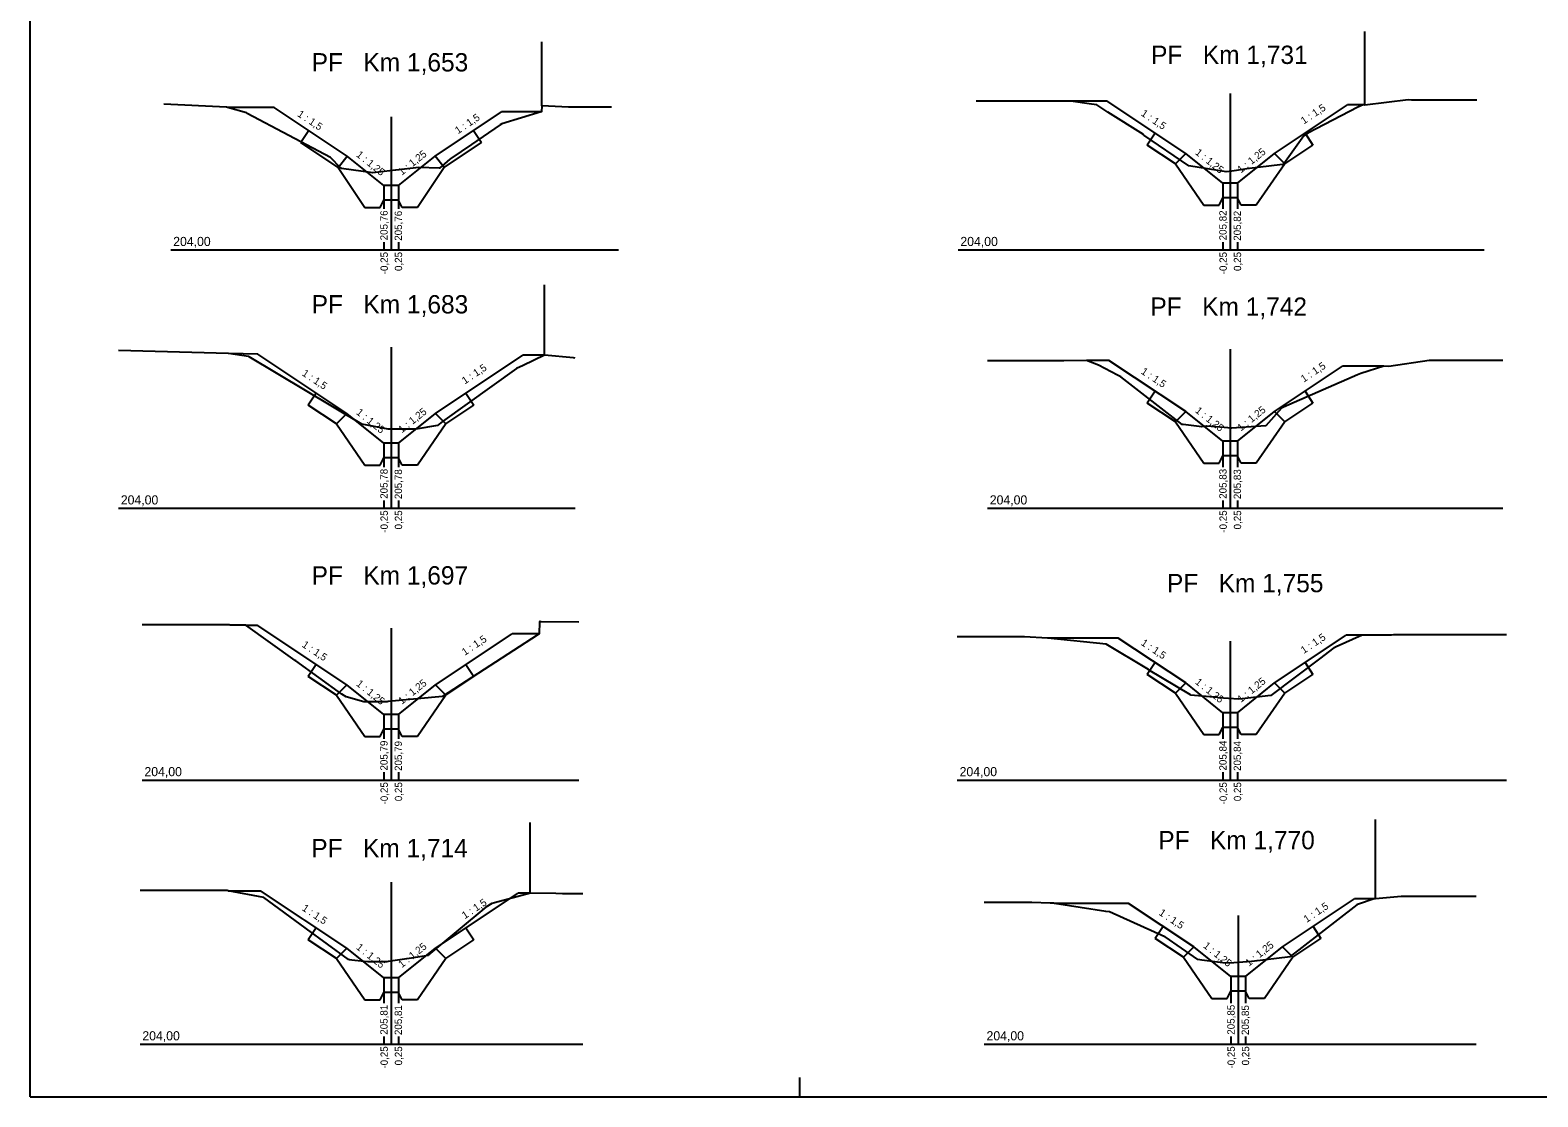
# Model space of a CAD drawing. Extents: x -547174 to -543113, y -1125006 to -1123643.
# Drawn here: x -547152.27 to -547111.11, y -1123837.37 to -1123808.23 of the extents above; entities that cross this region are included whole.
import ezdxf

# ---------------------------------------------------------------- set-up
doc = ezdxf.new("R2010")
doc.units = 0
for name, color, linetype in [('Default', 7, 'Continuous'), ('Profile', 7, 'Continuous'), ('PROFILY NÁVRH', 7, 'Continuous'), ('Section', 7, 'Continuous'), ('STANIČENÍ', 7, 'Continuous')]:
    doc.layers.add(name, color=color, linetype=linetype)

msp = doc.modelspace()

# ---------------------------------------------------------------- linework, layer by layer
at = {"layer": 'Default'}
for points in [[(-547136.405, -1123810.332), (-547137.568, -1123810.332), (-547137.573, -1123810.332), (-547138.304, -1123810.302), (-547138.315, -1123810.461), (-547138.326, -1123810.463), (-547139.398, -1123810.787), (-547139.438, -1123810.819), (-547140.228, -1123811.356), (-547140.789, -1123811.738), (-547140.818, -1123811.755), (-547141.1, -1123812.004), (-547141.1, -1123812.004), (-547141.102, -1123812.005), (-547141.662, -1123811.986), (-547141.665, -1123811.985), (-547142.292, -1123812.06), (-547142.296, -1123812.06), (-547142.92, -1123812.134), (-547143.769, -1123812.007), (-547143.79, -1123812.004), (-547144.072, -1123811.708), (-547146.344, -1123810.506), (-547146.366, -1123810.492), (-547146.368, -1123810.492), (-547146.886, -1123810.341), (-547146.909, -1123810.34), (-547148.627, -1123810.253)], [(-547112.776, -1123810.142), (-547114.563, -1123810.142), (-547114.649, -1123810.135), (-547115.838, -1123810.283), (-547115.868, -1123810.276), (-547115.884, -1123810.274), (-547116.029, -1123810.34), (-547117.389, -1123811.045), (-547117.497, -1123811.12), (-547118.049, -1123811.886), (-547118.06, -1123811.9), (-547118.082, -1123811.905), (-547119.054, -1123812.023), (-547119.34, -1123812.063), (-547119.341, -1123812.063), (-547119.463, -1123812.081), (-547119.62, -1123812.103), (-547120.637, -1123811.934), (-547120.637, -1123811.934), (-547121.868, -1123811.097), (-547121.882, -1123811.085), (-547122.856, -1123810.469), (-547123.156, -1123810.275), (-547123.158, -1123810.274), (-547123.159, -1123810.274), (-547123.364, -1123810.245), (-547123.866, -1123810.174), (-547123.899, -1123810.174), (-547126.444, -1123810.175)], [(-547137.392, -1123817.193), (-547137.44, -1123817.18), (-547138.228, -1123817.113), (-547138.809, -1123817.389), (-547138.997, -1123817.47), (-547141.014, -1123818.919), (-547141.154, -1123819.033), (-547141.74, -1123819.129), (-547141.762, -1123819.13), (-547142.117, -1123819.131), (-547142.125, -1123819.132), (-547142.48, -1123819.132), (-547142.486, -1123819.133), (-547142.5, -1123819.13), (-547143.218, -1123818.993), (-547146.289, -1123817.157), (-547146.311, -1123817.144), (-547146.854, -1123817.063), (-547146.854, -1123817.062), (-547146.857, -1123817.062), (-547149.86, -1123816.982)], [(-547112.067, -1123817.254), (-547114.077, -1123817.254), (-547115.178, -1123817.415), (-547115.316, -1123817.413), (-547115.944, -1123817.607), (-547116.037, -1123817.649), (-547118.053, -1123818.526), (-547118.111, -1123818.557), (-547118.542, -1123819.04), (-547118.543, -1123819.042), (-547119.47, -1123819.101), (-547119.477, -1123819.102), (-547119.675, -1123819.089), (-547120.151, -1123819.052), (-547120.156, -1123819.052), (-547120.282, -1123819.071), (-547120.791, -1123819.004), (-547120.819, -1123819.001), (-547122.495, -1123817.704), (-547122.497, -1123817.703), (-547122.584, -1123817.659), (-547123.107, -1123817.382), (-547123.433, -1123817.253), (-547124.051, -1123817.263), (-547124.062, -1123817.262), (-547126.138, -1123817.262)], [(-547137.295, -1123824.402), (-547138.333, -1123824.389), (-547138.351, -1123824.387), (-547138.369, -1123824.396), (-547138.374, -1123824.716), (-547138.427, -1123824.754), (-547141.013, -1123826.435), (-547142.5, -1123826.57), (-547142.522, -1123826.573), (-547142.857, -1123826.574), (-547142.864, -1123826.574), (-547143.157, -1123826.574), (-547143.164, -1123826.574), (-547143.647, -1123826.444), (-547143.648, -1123826.444), (-547143.759, -1123826.366), (-547145.02, -1123825.461), (-547145.04, -1123825.446), (-547146.384, -1123824.482), (-547146.81, -1123824.481), (-547146.839, -1123824.475), (-547147.014, -1123824.475), (-547149.215, -1123824.475)], [(-547111.971, -1123824.75), (-547115.052, -1123824.75), (-547115.108, -1123824.758), (-547115.91, -1123824.757), (-547116.616, -1123825.076), (-547116.675, -1123825.104), (-547116.678, -1123825.106), (-547117.069, -1123825.4), (-547118.4, -1123826.404), (-547119.184, -1123826.494), (-547119.271, -1123826.504), (-547119.557, -1123826.484), (-547119.559, -1123826.484), (-547119.844, -1123826.464), (-547119.849, -1123826.464), (-547119.859, -1123826.463), (-547120.583, -1123826.394), (-547120.591, -1123826.389), (-547121.737, -1123825.699), (-547121.746, -1123825.695), (-547122.894, -1123825.004), (-547124.49, -1123824.835), (-547124.495, -1123824.834), (-547124.497, -1123824.834), (-547125.131, -1123824.804), (-547125.191, -1123824.804), (-547126.961, -1123824.805)], [(-547137.184, -1123831.824), (-547137.741, -1123831.824), (-547137.923, -1123831.809), (-547138.615, -1123831.803), (-547139.598, -1123832.063), (-547139.673, -1123832.085), (-547139.828, -1123832.183), (-547141.396, -1123833.491), (-547141.409, -1123833.507), (-547141.864, -1123833.575), (-547142.495, -1123833.672), (-547142.501, -1123833.666), (-547142.539, -1123833.679), (-547142.84, -1123833.679), (-547142.842, -1123833.679), (-547143.056, -1123833.679), (-547143.057, -1123833.679), (-547143.152, -1123833.67), (-547143.488, -1123833.632), (-547143.557, -1123833.628), (-547143.579, -1123833.614), (-547144.724, -1123832.774), (-547144.765, -1123832.747), (-547145.894, -1123831.921), (-547146.865, -1123831.737), (-547146.891, -1123831.734), (-547147.073, -1123831.733), (-547149.272, -1123831.734)], [(-547112.8, -1123831.891), (-547114.844, -1123831.891), (-547115.547, -1123831.959), (-547115.581, -1123831.959), (-547116.04, -1123832.115), (-547116.058, -1123832.123), (-547117.552, -1123833.29), (-547117.87, -1123833.536), (-547117.873, -1123833.539), (-547118.922, -1123833.667), (-547118.93, -1123833.669), (-547118.933, -1123833.669), (-547119.286, -1123833.694), (-547119.286, -1123833.694), (-547119.416, -1123833.703), (-547119.643, -1123833.718), (-547120.286, -1123833.633), (-547120.393, -1123833.619), (-547121.291, -1123833), (-547121.294, -1123832.998), (-547121.298, -1123832.996), (-547122.803, -1123832.315), (-547122.909, -1123832.301), (-547124.312, -1123832.082), (-547124.334, -1123832.079), (-547124.422, -1123832.076), (-547124.924, -1123832.059), (-547124.927, -1123832.058), (-547126.226, -1123832.058)]]:
    msp.add_lwpolyline(points, dxfattribs=at)
at = {"layer": 'Profile'}
for p, q in [((-547152.272, -1123837.366), (-547152.272, -1123807.666)), ((-547131.272, -1123836.838), (-547131.272, -1123837.366)), ((-547152.272, -1123837.366), (-547131.272, -1123837.366)), ((-547131.272, -1123837.366), (-547110.272, -1123837.366))]:
    msp.add_line(p, q, dxfattribs=at)
at = {"layer": 'PROFILY NÁVRH'}
for p, q in [((-547145.614, -1123810.341), (-547146.886, -1123810.341)), ((-547143.615, -1123811.674), (-547145.614, -1123810.341)), ((-547122.867, -1123810.174), (-547123.866, -1123810.174)), ((-547120.725, -1123811.602), (-547122.867, -1123810.174)), ((-547118.301, -1123811.602), (-547116.309, -1123810.274)), ((-547115.884, -1123810.274), (-547116.309, -1123810.274)), ((-547141.22, -1123811.674), (-547139.403, -1123810.463)), ((-547138.326, -1123810.463), (-547139.403, -1123810.463)), ((-547144.663, -1123810.975), (-547144.88, -1123811.302)), ((-547140.173, -1123810.975), (-547139.955, -1123811.302)), ((-547121.557, -1123811.048), (-547121.775, -1123811.374)), ((-547117.469, -1123811.048), (-547117.252, -1123811.374)), ((-547143.861, -1123811.981), (-547144.88, -1123811.302)), ((-547140.974, -1123811.981), (-547139.955, -1123811.302)), ((-547121.008, -1123811.885), (-547121.775, -1123811.374)), ((-547121.008, -1123811.885), (-547120.725, -1123811.602)), ((-547119.713, -1123812.414), (-547120.725, -1123811.602)), ((-547119.313, -1123812.414), (-547118.301, -1123811.602)), ((-547118.018, -1123811.885), (-547118.301, -1123811.602)), ((-547118.018, -1123811.885), (-547117.252, -1123811.374)), ((-547143.861, -1123811.981), (-547143.615, -1123811.674)), ((-547143.861, -1123811.981), (-547143.133, -1123813.074)), ((-547142.618, -1123812.474), (-547143.615, -1123811.674)), ((-547142.218, -1123812.474), (-547141.22, -1123811.674)), ((-547140.974, -1123811.981), (-547141.702, -1123813.074)), ((-547140.974, -1123811.981), (-547141.22, -1123811.674)), ((-547121.008, -1123811.885), (-547120.228, -1123813.014)), ((-547118.018, -1123811.885), (-547118.798, -1123813.014)), ((-547119.313, -1123812.414), (-547119.713, -1123812.414)), ((-547119.713, -1123812.414), (-547119.713, -1123813.11)), ((-547119.313, -1123812.414), (-547119.313, -1123813.11)), ((-547142.718, -1123813.074), (-547142.618, -1123812.874)), ((-547142.218, -1123812.474), (-547142.618, -1123812.474)), ((-547142.618, -1123812.474), (-547142.618, -1123813.11)), ((-547142.218, -1123812.874), (-547142.618, -1123812.874)), ((-547142.218, -1123812.474), (-547142.218, -1123813.11)), ((-547142.118, -1123813.074), (-547142.218, -1123812.874)), ((-547119.813, -1123813.014), (-547119.713, -1123812.814)), ((-547119.313, -1123812.814), (-547119.713, -1123812.814)), ((-547119.213, -1123813.014), (-547119.313, -1123812.814)), ((-547143.133, -1123813.074), (-547142.718, -1123813.074)), ((-547141.702, -1123813.074), (-547142.118, -1123813.074)), ((-547120.228, -1123813.014), (-547119.813, -1123813.014)), ((-547118.798, -1123813.014), (-547119.213, -1123813.014)), ((-547142.618, -1123814.022), (-547142.618, -1123814.234)), ((-547142.218, -1123814.022), (-547142.218, -1123814.234)), ((-547119.713, -1123814.022), (-547119.713, -1123814.234)), ((-547119.313, -1123814.022), (-547119.313, -1123814.234)), ((-547146.054, -1123817.084), (-547146.857, -1123817.062)), ((-547143.629, -1123818.7), (-547146.054, -1123817.084)), ((-547141.206, -1123818.7), (-547138.825, -1123817.113)), ((-547138.228, -1123817.113), (-547138.825, -1123817.113)), ((-547122.82, -1123817.253), (-547123.433, -1123817.253)), ((-547120.725, -1123818.65), (-547122.82, -1123817.253)), ((-547118.301, -1123818.65), (-547116.445, -1123817.413)), ((-547115.316, -1123817.413), (-547116.445, -1123817.413)), ((-547144.461, -1123818.146), (-547144.679, -1123818.472)), ((-547140.374, -1123818.146), (-547140.156, -1123818.472)), ((-547121.557, -1123818.096), (-547121.775, -1123818.422)), ((-547117.469, -1123818.096), (-547117.252, -1123818.422)), ((-547143.912, -1123818.983), (-547144.679, -1123818.472)), ((-547140.923, -1123818.983), (-547140.156, -1123818.472)), ((-547121.008, -1123818.933), (-547121.775, -1123818.422)), ((-547118.018, -1123818.933), (-547117.252, -1123818.422)), ((-547143.912, -1123818.983), (-547143.629, -1123818.7)), ((-547143.912, -1123818.983), (-547143.133, -1123820.112)), ((-547142.618, -1123819.512), (-547143.629, -1123818.7)), ((-547142.218, -1123819.512), (-547141.206, -1123818.7)), ((-547140.923, -1123818.983), (-547141.702, -1123820.112)), ((-547140.923, -1123818.983), (-547141.206, -1123818.7)), ((-547121.008, -1123818.933), (-547120.725, -1123818.65)), ((-547121.008, -1123818.933), (-547120.228, -1123820.062)), ((-547119.713, -1123819.462), (-547120.725, -1123818.65)), ((-547119.313, -1123819.462), (-547118.301, -1123818.65)), ((-547118.018, -1123818.933), (-547118.798, -1123820.062)), ((-547118.018, -1123818.933), (-547118.301, -1123818.65)), ((-547119.313, -1123819.462), (-547119.713, -1123819.462)), ((-547119.713, -1123819.462), (-547119.713, -1123820.168)), ((-547119.313, -1123819.462), (-547119.313, -1123820.168)), ((-547142.218, -1123819.512), (-547142.618, -1123819.512)), ((-547142.618, -1123819.512), (-547142.618, -1123820.168)), ((-547142.218, -1123819.512), (-547142.218, -1123820.168)), ((-547119.813, -1123820.062), (-547119.713, -1123819.862)), ((-547119.313, -1123819.862), (-547119.713, -1123819.862)), ((-547119.213, -1123820.062), (-547119.313, -1123819.862)), ((-547143.133, -1123820.112), (-547142.718, -1123820.112)), ((-547142.718, -1123820.112), (-547142.618, -1123819.912)), ((-547142.218, -1123819.912), (-547142.618, -1123819.912)), ((-547142.118, -1123820.112), (-547142.218, -1123819.912)), ((-547141.702, -1123820.112), (-547142.118, -1123820.112)), ((-547120.228, -1123820.062), (-547119.813, -1123820.062)), ((-547118.798, -1123820.062), (-547119.213, -1123820.062)), ((-547142.618, -1123821.08), (-547142.618, -1123821.292)), ((-547142.218, -1123821.08), (-547142.218, -1123821.292)), ((-547119.713, -1123821.08), (-547119.713, -1123821.292)), ((-547119.313, -1123821.08), (-547119.313, -1123821.292)), ((-547146.384, -1123824.482), (-547146.075, -1123824.482)), ((-547143.629, -1123826.112), (-547146.075, -1123824.482)), ((-547141.206, -1123826.112), (-547139.111, -1123824.716)), ((-547138.374, -1123824.716), (-547139.111, -1123824.716)), ((-547118.301, -1123826.062), (-547116.344, -1123824.757)), ((-547115.91, -1123824.757), (-547116.344, -1123824.757)), ((-547122.566, -1123824.835), (-547124.49, -1123824.835)), ((-547120.725, -1123826.062), (-547122.566, -1123824.835)), ((-547144.461, -1123825.557), (-547144.679, -1123825.884)), ((-547140.374, -1123825.557), (-547140.156, -1123825.884)), ((-547121.557, -1123825.507), (-547121.775, -1123825.834)), ((-547117.469, -1123825.507), (-547117.252, -1123825.834)), ((-547143.912, -1123826.395), (-547144.679, -1123825.884)), ((-547140.923, -1123826.395), (-547140.156, -1123825.884)), ((-547121.008, -1123826.345), (-547121.775, -1123825.834)), ((-547118.018, -1123826.345), (-547117.252, -1123825.834)), ((-547143.912, -1123826.395), (-547143.629, -1123826.112)), ((-547143.912, -1123826.395), (-547143.133, -1123827.524)), ((-547142.618, -1123826.924), (-547143.629, -1123826.112)), ((-547142.218, -1123826.924), (-547141.206, -1123826.112)), ((-547140.923, -1123826.395), (-547141.702, -1123827.524)), ((-547140.923, -1123826.395), (-547141.206, -1123826.112)), ((-547121.008, -1123826.345), (-547120.725, -1123826.062)), ((-547121.008, -1123826.345), (-547120.228, -1123827.474)), ((-547119.713, -1123826.874), (-547120.725, -1123826.062)), ((-547119.313, -1123826.874), (-547118.301, -1123826.062)), ((-547118.018, -1123826.345), (-547118.798, -1123827.474)), ((-547118.018, -1123826.345), (-547118.301, -1123826.062)), ((-547119.313, -1123826.874), (-547119.713, -1123826.874)), ((-547119.713, -1123826.874), (-547119.713, -1123827.59)), ((-547119.313, -1123826.874), (-547119.313, -1123827.59)), ((-547142.218, -1123826.924), (-547142.618, -1123826.924)), ((-547142.618, -1123826.924), (-547142.618, -1123827.59)), ((-547142.218, -1123826.924), (-547142.218, -1123827.59)), ((-547119.813, -1123827.474), (-547119.713, -1123827.274)), ((-547119.313, -1123827.274), (-547119.713, -1123827.274)), ((-547119.213, -1123827.474), (-547119.313, -1123827.274)), ((-547143.133, -1123827.524), (-547142.718, -1123827.524)), ((-547142.718, -1123827.524), (-547142.618, -1123827.324)), ((-547142.218, -1123827.324), (-547142.618, -1123827.324)), ((-547142.118, -1123827.524), (-547142.218, -1123827.324)), ((-547141.702, -1123827.524), (-547142.118, -1123827.524)), ((-547120.228, -1123827.474), (-547119.813, -1123827.474)), ((-547118.798, -1123827.474), (-547119.213, -1123827.474)), ((-547142.618, -1123828.502), (-547142.618, -1123828.714)), ((-547142.218, -1123828.502), (-547142.218, -1123828.714)), ((-547119.713, -1123828.502), (-547119.713, -1123828.714)), ((-547119.313, -1123828.502), (-547119.313, -1123828.714)), ((-547146.865, -1123831.737), (-547145.984, -1123831.737)), ((-547143.629, -1123833.307), (-547145.984, -1123831.737)), ((-547141.206, -1123833.307), (-547138.95, -1123831.803)), ((-547138.615, -1123831.803), (-547138.95, -1123831.803)), ((-547122.284, -1123832.082), (-547124.312, -1123832.082)), ((-547120.506, -1123833.267), (-547122.284, -1123832.082)), ((-547118.082, -1123833.267), (-547116.12, -1123831.959)), ((-547115.581, -1123831.959), (-547116.12, -1123831.959)), ((-547144.461, -1123832.752), (-547144.679, -1123833.078)), ((-547140.374, -1123832.752), (-547140.156, -1123833.078)), ((-547121.338, -1123832.712), (-547121.555, -1123833.038)), ((-547120.789, -1123833.55), (-547121.555, -1123833.038)), ((-547117.799, -1123833.55), (-547117.033, -1123833.038)), ((-547117.25, -1123832.712), (-547117.033, -1123833.038)), ((-547143.912, -1123833.59), (-547144.679, -1123833.078)), ((-547143.912, -1123833.59), (-547143.629, -1123833.307)), ((-547142.618, -1123834.119), (-547143.629, -1123833.307)), ((-547142.218, -1123834.119), (-547141.206, -1123833.307)), ((-547140.923, -1123833.59), (-547141.206, -1123833.307)), ((-547140.923, -1123833.59), (-547140.156, -1123833.078)), ((-547120.789, -1123833.55), (-547120.506, -1123833.267)), ((-547119.494, -1123834.079), (-547120.506, -1123833.267)), ((-547119.094, -1123834.079), (-547118.082, -1123833.267)), ((-547117.799, -1123833.55), (-547118.082, -1123833.267)), ((-547143.912, -1123833.59), (-547143.133, -1123834.719)), ((-547140.923, -1123833.59), (-547141.702, -1123834.719)), ((-547120.789, -1123833.55), (-547120.009, -1123834.679)), ((-547117.799, -1123833.55), (-547118.579, -1123834.679)), ((-547142.218, -1123834.119), (-547142.618, -1123834.119)), ((-547142.618, -1123834.119), (-547142.618, -1123834.804)), ((-547142.218, -1123834.119), (-547142.218, -1123834.804)), ((-547119.094, -1123834.079), (-547119.494, -1123834.079)), ((-547119.494, -1123834.079), (-547119.494, -1123834.804)), ((-547119.094, -1123834.079), (-547119.094, -1123834.804)), ((-547142.718, -1123834.719), (-547142.618, -1123834.519)), ((-547142.218, -1123834.519), (-547142.618, -1123834.519)), ((-547142.118, -1123834.719), (-547142.218, -1123834.519)), ((-547120.009, -1123834.679), (-547119.594, -1123834.679)), ((-547119.594, -1123834.679), (-547119.494, -1123834.479)), ((-547119.094, -1123834.479), (-547119.494, -1123834.479)), ((-547118.994, -1123834.679), (-547119.094, -1123834.479)), ((-547118.579, -1123834.679), (-547118.994, -1123834.679)), ((-547143.133, -1123834.719), (-547142.718, -1123834.719)), ((-547141.702, -1123834.719), (-547142.118, -1123834.719)), ((-547142.618, -1123835.716), (-547142.618, -1123835.929)), ((-547142.218, -1123835.716), (-547142.218, -1123835.929)), ((-547119.494, -1123835.716), (-547119.494, -1123835.929)), ((-547119.094, -1123835.716), (-547119.094, -1123835.929))]:
    msp.add_line(p, q, dxfattribs=at)
at = {"layer": 'Section'}
for p, q in [((-547119.513, -1123809.966), (-547119.513, -1123814.234)), ((-547142.418, -1123810.602), (-547142.418, -1123814.234)), ((-547148.431, -1123814.234), (-547136.208, -1123814.234)), ((-547126.94, -1123814.234), (-547112.582, -1123814.234)), ((-547142.418, -1123816.892), (-547142.418, -1123821.292)), ((-547119.513, -1123816.947), (-547119.513, -1123821.292)), ((-547149.86, -1123821.292), (-547137.392, -1123821.292)), ((-547126.138, -1123821.292), (-547112.067, -1123821.292)), ((-547142.418, -1123824.564), (-547142.418, -1123828.714)), ((-547119.513, -1123824.919), (-547119.513, -1123828.714)), ((-547149.215, -1123828.714), (-547137.295, -1123828.714)), ((-547126.961, -1123828.714), (-547111.971, -1123828.714)), ((-547142.418, -1123831.501), (-547142.418, -1123835.929)), ((-547119.294, -1123832.41), (-547119.294, -1123835.929)), ((-547149.272, -1123835.929), (-547137.184, -1123835.929)), ((-547126.226, -1123835.929), (-547112.8, -1123835.929))]:
    msp.add_line(p, q, dxfattribs=at)
at = {"layer": 'STANIČENÍ'}
for p, q in [((-547115.838, -1123810.283), (-547115.838, -1123808.271)), ((-547138.304, -1123810.302), (-547138.304, -1123808.554)), ((-547138.228, -1123817.113), (-547138.228, -1123815.186)), ((-547138.618, -1123831.803), (-547138.618, -1123829.876)), ((-547115.547, -1123831.959), (-547115.547, -1123829.793))]:
    msp.add_line(p, q, dxfattribs=at)

# ---------------------------------------------------------------- texts
at = {"layer": 'PROFILY NÁVRH'}
for s, rotation, p in [('1 : 1,5', 33.6901, (-547117.501, -1123810.812)), ('1 : 1,5', 326.3099, (-547144.994, -1123810.57)), ('1 : 1,5', 33.6901, (-547140.592, -1123811.077)), ('1 : 1,5', 326.3099, (-547121.963, -1123810.551)), ('1 : 1,25', 321.2587, (-547143.388, -1123811.666)), ('1 : 1,25', 38.7413, (-547142.123, -1123812.208)), ('1 : 1,25', 321.2587, (-547120.483, -1123811.606)), ('1 : 1,25', 38.7413, (-547119.218, -1123812.148)), ('205,76', 90, (-547142.514, -1123813.974)), ('205,76', 90, (-547142.122, -1123813.985)), ('205,82', 90, (-547119.61, -1123813.974)), ('205,82', 90, (-547119.218, -1123813.985)), ('-0,25', 90, (-547142.508, -1123814.9)), ('0,25', 90, (-547142.117, -1123814.811)), ('-0,25', 90, (-547119.604, -1123814.9)), ('0,25', 90, (-547119.212, -1123814.811)), ('1 : 1,5', 33.6901, (-547140.405, -1123817.911)), ('1 : 1,5', 33.6901, (-547117.501, -1123817.861)), ('1 : 1,5', 326.3099, (-547144.868, -1123817.649)), ('1 : 1,5', 326.3099, (-547121.963, -1123817.599)), ('1 : 1,25', 321.2587, (-547143.388, -1123818.704)), ('1 : 1,25', 38.7413, (-547142.123, -1123819.246)), ('1 : 1,25', 321.2587, (-547120.483, -1123818.654)), ('1 : 1,25', 38.7413, (-547119.218, -1123819.196)), ('205,78', 90, (-547142.514, -1123821.032)), ('205,78', 90, (-547142.122, -1123821.043)), ('205,83', 90, (-547119.61, -1123821.032)), ('205,83', 90, (-547119.218, -1123821.043)), ('-0,25', 90, (-547142.508, -1123821.958)), ('0,25', 90, (-547142.117, -1123821.869)), ('-0,25', 90, (-547119.604, -1123821.958)), ('0,25', 90, (-547119.212, -1123821.869)), ('1 : 1,5', 33.6901, (-547140.405, -1123825.322)), ('1 : 1,5', 33.6901, (-547117.501, -1123825.272)), ('1 : 1,5', 326.3099, (-547144.868, -1123825.061)), ('1 : 1,5', 326.3099, (-547121.963, -1123825.011)), ('1 : 1,25', 321.2587, (-547143.388, -1123826.116)), ('1 : 1,25', 38.7413, (-547142.123, -1123826.658)), ('1 : 1,25', 321.2587, (-547120.483, -1123826.066)), ('1 : 1,25', 38.7413, (-547119.218, -1123826.608)), ('205,79', 90, (-547142.514, -1123828.454)), ('205,79', 90, (-547142.122, -1123828.465)), ('205,84', 90, (-547119.61, -1123828.454)), ('205,84', 90, (-547119.218, -1123828.465)), ('-0,25', 90, (-547142.508, -1123829.38)), ('0,25', 90, (-547142.117, -1123829.291)), ('-0,25', 90, (-547119.604, -1123829.38)), ('0,25', 90, (-547119.212, -1123829.291)), ('1 : 1,5', 326.3099, (-547144.868, -1123832.256)), ('1 : 1,5', 33.6901, (-547140.405, -1123832.517)), ('1 : 1,5', 33.6901, (-547117.424, -1123832.617)), ('1 : 1,5', 326.3099, (-547121.475, -1123832.382)), ('1 : 1,25', 321.2587, (-547143.388, -1123833.311)), ('1 : 1,25', 38.7413, (-547142.123, -1123833.852)), ('1 : 1,25', 321.2587, (-547120.264, -1123833.271)), ('1 : 1,25', 38.7413, (-547118.999, -1123833.812)), ('205,81', 90, (-547142.514, -1123835.669)), ('205,81', 90, (-547142.122, -1123835.679)), ('205,85', 90, (-547119.39, -1123835.669)), ('205,85', 90, (-547118.999, -1123835.679)), ('-0,25', 90, (-547142.508, -1123836.594)), ('0,25', 90, (-547142.117, -1123836.506)), ('-0,25', 90, (-547119.385, -1123836.594)), ('0,25', 90, (-547118.993, -1123836.506))]:
    msp.add_text(s, height=0.2, rotation=rotation, dxfattribs=at).set_placement(p)
at = {"layer": 'Section'}
for s, height, p in [('PF   Km 1,731', 0.5, (-547121.67, -1123809.156)), ('PF   Km 1,653', 0.5, (-547144.586, -1123809.361)), ('204,00', 0.25, (-547148.367, -1123814.129)), ('204,00', 0.25, (-547126.877, -1123814.129)), ('PF   Km 1,683', 0.5, (-547144.586, -1123815.97)), ('PF   Km 1,742', 0.5, (-547121.688, -1123816.034)), ('204,00', 0.25, (-547149.797, -1123821.187)), ('204,00', 0.25, (-547126.074, -1123821.187)), ('PF   Km 1,697', 0.5, (-547144.589, -1123823.373)), ('PF   Km 1,755', 0.5, (-547121.238, -1123823.584)), ('204,00', 0.25, (-547149.152, -1123828.609)), ('204,00', 0.25, (-547126.898, -1123828.609)), ('PF   Km 1,770', 0.5, (-547121.475, -1123830.604)), ('PF   Km 1,714', 0.5, (-547144.598, -1123830.822)), ('204,00', 0.25, (-547149.209, -1123835.823)), ('204,00', 0.25, (-547126.163, -1123835.823))]:
    msp.add_text(s, height=height, dxfattribs=at).set_placement(p)

doc.saveas('drawing.dxf')
